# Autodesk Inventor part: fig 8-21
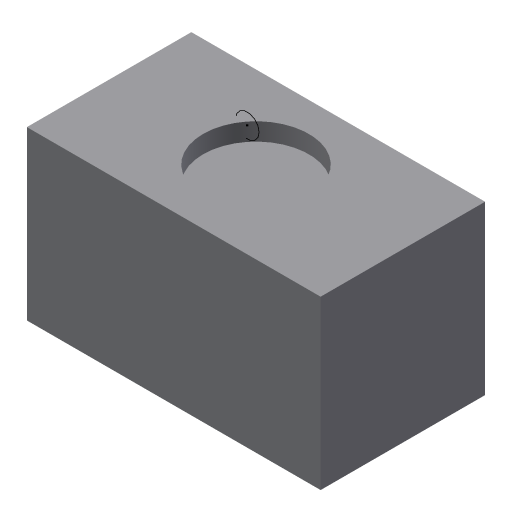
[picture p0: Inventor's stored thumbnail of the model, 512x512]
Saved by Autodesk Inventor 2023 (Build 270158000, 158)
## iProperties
Created: 2011-07
Part Number: fig 8-21
Material: Generic
Document SubType Name: Modeling
Designer: CadCim
Density: 1 g/cm^3
Appearance: Default
Author: CadCim
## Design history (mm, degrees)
sketch "Sketch1"
  geometry: L1 (-18, 10)-(7, 10); L2 (7, 10)-(7, -4); L3 (7, -4)-(-18, -4); L4 (-18, -4)-(-18, 10); 1 further point
  constraints: 8 end point, 2 parallel, 1 horizontal, 1 perpendicular
extrude "Extrusion1" new body sketch "Sketch1" distance "d0" = 14.25; taper "d1" = 0 deg
sketch "Sketch2"
  geometry: C1 r 4.5 at (-5.5, 3); 1 further point
  constraints: 1 centre point
extrude "Extrusion2" cut sketch "Sketch2" distance "d2" = 1.5; taper "d3" = 0 deg
workplane "Work Plane2"
sketch "Sketch4"
  geometry: C1 r 1 at (9, -14); 1 further point
  constraints: 1 centre point
body "Solid1"
other parameters: "d4" = -4.25
